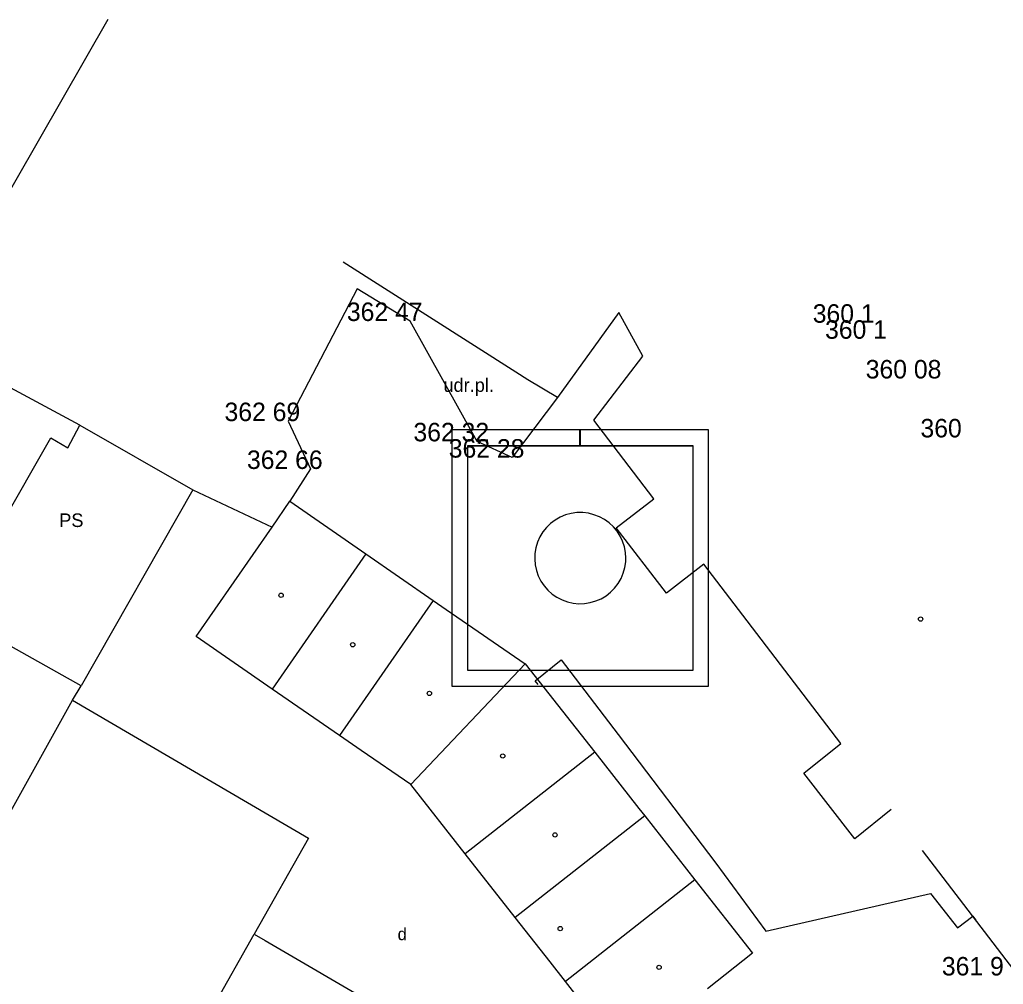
# Model space of a CAD drawing. Extents: x -688316 to -688024, y -973785 to -973591.
# Drawn here: x -688108.72 to -688068.85, y -973630.22 to -973591.1 of the extents above; entities that cross this region are included whole.
import ezdxf

# ---------------------------------------------------------------- set-up
doc = ezdxf.new("R2010")
doc.units = 0
for name, color, linetype in [('Vrstva 10', 7, 'Continuous'), ('Vrstva 1_elektro CEZ', 7, 'Continuous'), ('Vrstva 3', 7, 'Continuous'), ('Vrstva 36', 7, 'Continuous'), ('Vrstva 40', 7, 'Continuous'), ('Vrstva 41', 7, 'Continuous'), ('Vrstva 5', 7, 'Continuous'), ('Vrstva 58', 7, 'Continuous'), ('Vrstva 7', 7, 'Continuous')]:
    doc.layers.add(name, color=color, linetype=linetype)

# ---------------------------------------------------------------- blocks, each defined once
blk = doc.blocks.new('B_NESP')
at = {"layer": 'Vrstva 58'}
blk.add_circle((0, 0), 0.875, dxfattribs=at)
blk = doc.blocks.new('ZKUDR0')
at = {"layer": 'Vrstva 40'}
blk.add_text('udr.pl.', height=5.5, dxfattribs=at).set_placement((-11.71, -3.04))
blk = doc.blocks.new('SKPOV0')
at = {"layer": 'Vrstva 41'}
blk.add_text('PS', height=5.5, dxfattribs=at).set_placement((-6.25, -3.04))
blk = doc.blocks.new('DVUR')
at = {"layer": 'Vrstva 36'}
blk.add_text('d', height=5, dxfattribs=at).set_placement((-1.69, -2.5))
blk = doc.blocks.new('X43_1')
at = {"layer": 'Vrstva 2'}
blk.add_lwpolyline([(36.96, 0), (36.68, 4.66), (35.8, 9.24), (34.34, 13.7), (32.32, 17.92), (29.82, 21.86), (26.82, 25.44), (23.4, 28.62), (19.6, 31.36), (15.48, 33.56), (11.12, 35.24), (6.6, 36.38), (1.96, 36.92), (-2.72, 36.88), (-7.36, 36.24), (-11.88, 35), (-16.2, 33.24), (-20.26, 30.92), (-24, 28.12), (-27.36, 24.88), (-30.28, 21.22), (-32.72, 17.24), (-34.62, 12.96), (-35.98, 8.48), (-36.76, 3.88), (-36.96, -0.78), (-36.56, -5.44), (-35.6, -10), (-34.04, -14.42), (-31.96, -18.6), (-29.34, -22.48), (-26.28, -26), (-22.78, -29.12), (-18.92, -31.76), (-14.76, -33.88), (-10.36, -35.48), (-5.8, -36.52), (-1.16, -36.96), (3.52, -36.8), (8.12, -36.06), (12.6, -34.76), (16.88, -32.88), (20.92, -30.48), (24.6, -27.6), (27.88, -24.28), (30.72, -20.56), (33.08, -16.52), (34.88, -12.24), (36.16, -7.72), (36.84, -3.1)], close=True, dxfattribs=at)
blk.add_lwpolyline([(36.96, 0), (36.68, 4.66), (35.8, 9.24), (34.34, 13.7), (32.32, 17.92), (29.82, 21.86), (26.82, 25.44), (23.4, 28.62), (19.6, 31.36), (15.48, 33.56), (11.12, 35.24), (6.6, 36.38), (1.96, 36.92), (-2.72, 36.88), (-7.36, 36.24), (-11.88, 35), (-16.2, 33.24), (-20.26, 30.92), (-24, 28.12), (-27.36, 24.88), (-30.28, 21.22), (-32.72, 17.24), (-34.62, 12.96), (-35.98, 8.48), (-36.76, 3.88), (-36.96, -0.78), (-36.56, -5.44), (-35.6, -10), (-34.04, -14.42), (-31.96, -18.6), (-29.34, -22.48), (-26.28, -26), (-22.78, -29.12), (-18.92, -31.76), (-14.76, -33.88), (-10.36, -35.48), (-5.8, -36.52), (-1.16, -36.96), (3.52, -36.8), (8.12, -36.06), (12.6, -34.76), (16.88, -32.88), (20.92, -30.48), (24.6, -27.6), (27.88, -24.28), (30.72, -20.56), (33.08, -16.52), (34.88, -12.24), (36.16, -7.72), (36.84, -3.1), (36.96, 0)], dxfattribs=at)
at = {"layer": 'Vrstva 3'}
for points in [[(-0.24, 104.04), (-104, 104.04), (-104, -103.96), (104, -103.96), (104, 104.04), (0, 104.04), (0, 91.24), (91.2, 91.24), (91.2, -91.16), (-91.2, -91.16), (-91.2, 91.24), (-0.24, 91.24)], [(-91.2, 91.2), (91.2, 91.2), (91.2, -91.2), (-91.2, -91.2)]]:
    blk.add_lwpolyline(points, close=True, dxfattribs=at)
blk.add_lwpolyline([(-0.24, 104.04), (-104, 104.04), (-104, -103.96), (104, -103.96), (104, 104.04), (0, 104.04), (0, 91.24), (91.2, 91.24), (91.2, -91.16), (-91.2, -91.16), (-91.2, 91.24), (-0.24, 91.24), (-0.24, 104.04)], dxfattribs=at)
blk = doc.blocks.new('472001')
at = {"layer": 'Vrstva 3'}
blk.add_blockref('X43_1', (0, 0), dxfattribs=at)

msp = doc.modelspace()

# ---------------------------------------------------------------- linework, layer by layer
at = {"layer": 'Vrstva 10'}
for points in [[(-688086.92, -973606.42), (-688088.76, -973608.86), (-688090.18, -973608.2), (-688092.89, -973603.32), (-688095.04, -973602.02), (-688097.84, -973607.38)], [(-688097.84, -973607.38), (-688096.93, -973609.32), (-688097.77, -973610.63)]]:
    msp.add_lwpolyline(points, dxfattribs=at)
at = {"layer": 'Vrstva 1_elektro CEZ'}
msp.add_lwpolyline([(-688087.7, -973618.065), (-688087.825, -973617.909), (-688086.773, -973617.067), (-688084.465, -973620.086), (-688080.496, -973625.307), (-688078.476, -973628.058), (-688071.794, -973626.542), (-688070.704, -973627.932), (-688070.078, -973627.454), (-688069.956, -973627.613)], dxfattribs=at)
at = {"layer": 'Vrstva 5'}
for p, q in [((-688088.61, -973605.39), (-688095.6, -973600.93)), ((-688084.43, -973602.97), (-688086.92, -973606.42)), ((-688083.46, -973604.74), (-688084.43, -973602.97)), ((-688085.44, -973607.34), (-688083.46, -973604.74)), ((-688088.12, -973605.71), (-688088.61, -973605.39)), ((-688086.92, -973606.42), (-688088.12, -973605.71)), ((-688083.01, -973610.53), (-688085.44, -973607.34)), ((-688098.49, -973611.68), (-688097.77, -973610.63)), ((-688097.77, -973610.63), (-688094.69, -973612.76)), ((-688084.54, -973611.71), (-688083.01, -973610.53)), ((-688101.56, -973616.12), (-688098.49, -973611.68)), ((-688082.5, -973614.36), (-688084.54, -973611.71)), ((-688094.69, -973612.76), (-688098.48, -973618.25)), ((-688094.69, -973612.76), (-688091.96, -973614.65)), ((-688080.99, -973613.18), (-688082.5, -973614.36)), ((-688079.4, -973615.25), (-688080.99, -973613.18)), ((-688091.96, -973614.65), (-688095.75, -973620.13)), ((-688091.96, -973614.65), (-688091.43, -973615.02)), ((-688091.43, -973615.02), (-688088.23, -973617.22)), ((-688075.44, -973620.45), (-688079.4, -973615.25)), ((-688098.48, -973618.25), (-688101.56, -973616.12)), ((-688088.23, -973617.22), (-688092.87, -973622.12)), ((-688088.23, -973617.22), (-688085.41, -973620.81)), ((-688095.75, -973620.13), (-688098.48, -973618.25)), ((-688110.61, -973625.94), (-688106.58, -973618.7)), ((-688106.58, -973618.7), (-688097.01, -973624.29)), ((-688094.87, -973620.74), (-688095.75, -973620.13)), ((-688092.87, -973622.12), (-688094.87, -973620.74)), ((-688076.93, -973621.66), (-688075.44, -973620.45)), ((-688085.41, -973620.81), (-688090.66, -973624.93)), ((-688085.41, -973620.81), (-688083.62, -973623.09)), ((-688074.87, -973624.32), (-688076.93, -973621.66)), ((-688090.66, -973624.93), (-688092.87, -973622.12)), ((-688083.62, -973623.09), (-688083.38, -973623.39)), ((-688073.39, -973623.13), (-688074.87, -973624.32)), ((-688083.38, -973623.39), (-688088.63, -973627.51)), ((-688083.38, -973623.39), (-688081.35, -973625.98)), ((-688097.01, -973624.29), (-688099.22, -973628.18)), ((-688068.24, -973629.86), (-688072.13, -973624.79)), ((-688088.63, -973627.51), (-688090.66, -973624.93)), ((-688081.35, -973625.98), (-688086.6, -973630.1)), ((-688081.35, -973625.98), (-688079.01, -973628.96)), ((-688087.22, -973629.31), (-688088.63, -973627.51)), ((-688108.26, -973644.21), (-688099.22, -973628.18)), ((-688099.22, -973628.18), (-688098.77, -973628.44)), ((-688098.77, -973628.44), (-688093.85, -973631.31)), ((-688079.01, -973628.96), (-688080.84, -973630.4)), ((-688086.6, -973630.1), (-688087.22, -973629.31)), ((-688084.25, -973633.08), (-688086.6, -973630.1))]:
    msp.add_line(p, q, dxfattribs=at)
msp.add_lwpolyline([(-688105.15, -973591.1), (-688112.62, -973604.13), (-688113.2, -973605.14), (-688115.32, -973604)], dxfattribs=at)
at = {"layer": 'Vrstva 7'}
for p, q in [((-688106.28, -973607.55), (-688112.62, -973604.13)), ((-688106.76, -973608.47), (-688106.28, -973607.55)), ((-688106.28, -973607.55), (-688101.7, -973610.16)), ((-688109.47, -973611.58), (-688107.46, -973608.06)), ((-688107.46, -973608.06), (-688106.76, -973608.47)), ((-688101.7, -973610.16), (-688106.23, -973618.12)), ((-688101.7, -973610.16), (-688098.49, -973611.68)), ((-688106.23, -973618.12), (-688110.82, -973615.54)), ((-688106.58, -973618.7), (-688106.23, -973618.12))]:
    msp.add_line(p, q, dxfattribs=at)

# ---------------------------------------------------------------- block references
at = {"layer": 'Vrstva 3', "xscale": 0.05, "yscale": 0.05000000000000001}
msp.add_blockref('472001', (-688085.996, -973612.936), dxfattribs=at)
at = {"layer": 'Vrstva 36', "xscale": 0.1, "yscale": 0.10000000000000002}
msp.add_blockref('DVUR', (-688093.23, -973628.18), dxfattribs=at)
at = {"layer": 'Vrstva 40', "xscale": 0.1, "yscale": 0.10000000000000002}
msp.add_blockref('ZKUDR0', (-688090.37, -973605.89), dxfattribs=at)
at = {"layer": 'Vrstva 41', "xscale": 0.1, "yscale": 0.10000000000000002}
msp.add_blockref('SKPOV0', (-688106.49, -973611.37), dxfattribs=at)
at = {"layer": 'Vrstva 58', "xscale": 0.1, "yscale": 0.10000000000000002}
for p in [(-688098.12, -973614.44), (-688098.12, -973614.44), (-688098.12, -973614.44), (-688098.12, -973614.44), (-688072.2, -973615.41), (-688072.2, -973615.41), (-688072.2, -973615.41), (-688072.2, -973615.41), (-688095.22, -973616.45), (-688095.22, -973616.45), (-688095.22, -973616.45), (-688095.22, -973616.45), (-688092.11, -973618.42), (-688092.11, -973618.42), (-688092.11, -973618.42), (-688092.11, -973618.42), (-688089.14, -973620.96), (-688089.14, -973620.96), (-688089.14, -973620.96), (-688089.14, -973620.96), (-688087.02, -973624.16), (-688087.02, -973624.16), (-688087.02, -973624.16), (-688087.02, -973624.16), (-688086.81, -973627.96), (-688086.81, -973627.96), (-688086.81, -973627.96), (-688086.81, -973627.96), (-688082.8, -973629.53), (-688082.8, -973629.53), (-688082.8, -973629.53), (-688082.8, -973629.53)]:
    msp.add_blockref('B_NESP', p, dxfattribs=at)

# ---------------------------------------------------------------- texts
at = {"layer": 'Vrstva 3'}
for s, p in [('362 47 ', (-688095.456, -973603.32)), ('362 47 ', (-688095.456, -973603.32)), ('362 47 ', (-688095.456, -973603.32)), ('362 47 ', (-688095.456, -973603.32)), ('362 47 ', (-688095.456, -973603.32)), ('362 47 ', (-688095.456, -973603.32)), ('362 47 ', (-688095.456, -973603.32)), ('360 1  ', (-688076.573, -973603.39)), ('360 1  ', (-688076.573, -973603.39)), ('360 1  ', (-688076.573, -973603.39)), ('360 1  ', (-688076.573, -973603.39)), ('360 1  ', (-688076.573, -973603.39)), ('360 1  ', (-688076.573, -973603.39)), ('360 1  ', (-688076.573, -973603.39)), ('360 1  ', (-688076.073, -973604.04)), ('360 1  ', (-688076.073, -973604.04)), ('360 1  ', (-688076.073, -973604.04)), ('360 1  ', (-688076.073, -973604.04)), ('360 1  ', (-688076.073, -973604.04)), ('360 1  ', (-688076.073, -973604.04)), ('360 1  ', (-688076.073, -973604.04)), ('360 08 ', (-688074.426, -973605.65)), ('360 08 ', (-688074.426, -973605.65)), ('360 08 ', (-688074.426, -973605.65)), ('360 08 ', (-688074.426, -973605.65)), ('360 08 ', (-688074.426, -973605.65)), ('360 08 ', (-688074.426, -973605.65)), ('360 08 ', (-688074.426, -973605.65)), ('362 69 ', (-688100.415, -973607.38)), ('362 69 ', (-688100.415, -973607.38)), ('362 69 ', (-688100.415, -973607.38)), ('362 69 ', (-688100.415, -973607.38)), ('362 69 ', (-688100.415, -973607.38)), ('362 69 ', (-688100.415, -973607.38)), ('362 69 ', (-688100.415, -973607.38)), ('362 32 ', (-688092.758, -973608.2)), ('362 32 ', (-688092.758, -973608.2)), ('362 32 ', (-688092.758, -973608.2)), ('362 32 ', (-688092.758, -973608.2)), ('362 32 ', (-688092.758, -973608.2)), ('362 32 ', (-688092.758, -973608.2)), ('362 32 ', (-688092.758, -973608.2)), ('360    ', (-688072.207, -973608.04)), ('360    ', (-688072.207, -973608.04)), ('360    ', (-688072.207, -973608.04)), ('360    ', (-688072.207, -973608.04)), ('360    ', (-688072.207, -973608.04)), ('360    ', (-688072.207, -973608.04)), ('360    ', (-688072.207, -973608.04)), ('362 28 ', (-688091.326, -973608.86)), ('362 28 ', (-688091.326, -973608.86)), ('362 28 ', (-688091.326, -973608.86)), ('362 28 ', (-688091.326, -973608.86)), ('362 28 ', (-688091.326, -973608.86)), ('362 28 ', (-688091.326, -973608.86)), ('362 28 ', (-688091.326, -973608.86)), ('362 66 ', (-688099.505, -973609.32)), ('362 66 ', (-688099.505, -973609.32)), ('362 66 ', (-688099.505, -973609.32)), ('362 66 ', (-688099.505, -973609.32)), ('362 66 ', (-688099.505, -973609.32)), ('362 66 ', (-688099.505, -973609.32)), ('362 66 ', (-688099.505, -973609.32)), ('361 9  ', (-688071.339, -973629.86)), ('361 9  ', (-688071.339, -973629.86)), ('361 9  ', (-688071.339, -973629.86)), ('361 9  ', (-688071.339, -973629.86)), ('361 9  ', (-688071.339, -973629.86)), ('361 9  ', (-688071.339, -973629.86)), ('361 9  ', (-688071.339, -973629.86))]:
    msp.add_text(s, height=0.75, dxfattribs=at).set_placement(p)

doc.saveas('drawing.dxf')
